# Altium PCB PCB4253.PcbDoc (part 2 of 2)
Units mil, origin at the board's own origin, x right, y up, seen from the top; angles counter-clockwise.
Board outline 1181.1 x 2007.87 mil, 6 copper layers (Top Layer, Signal Layer 2, GND Layer 3, PWR Layer 4, Signal Layer 5, Bottom Layer), stack 65.197 mil thick; 84 components, 108 nets, 396 pads, 435 vias.
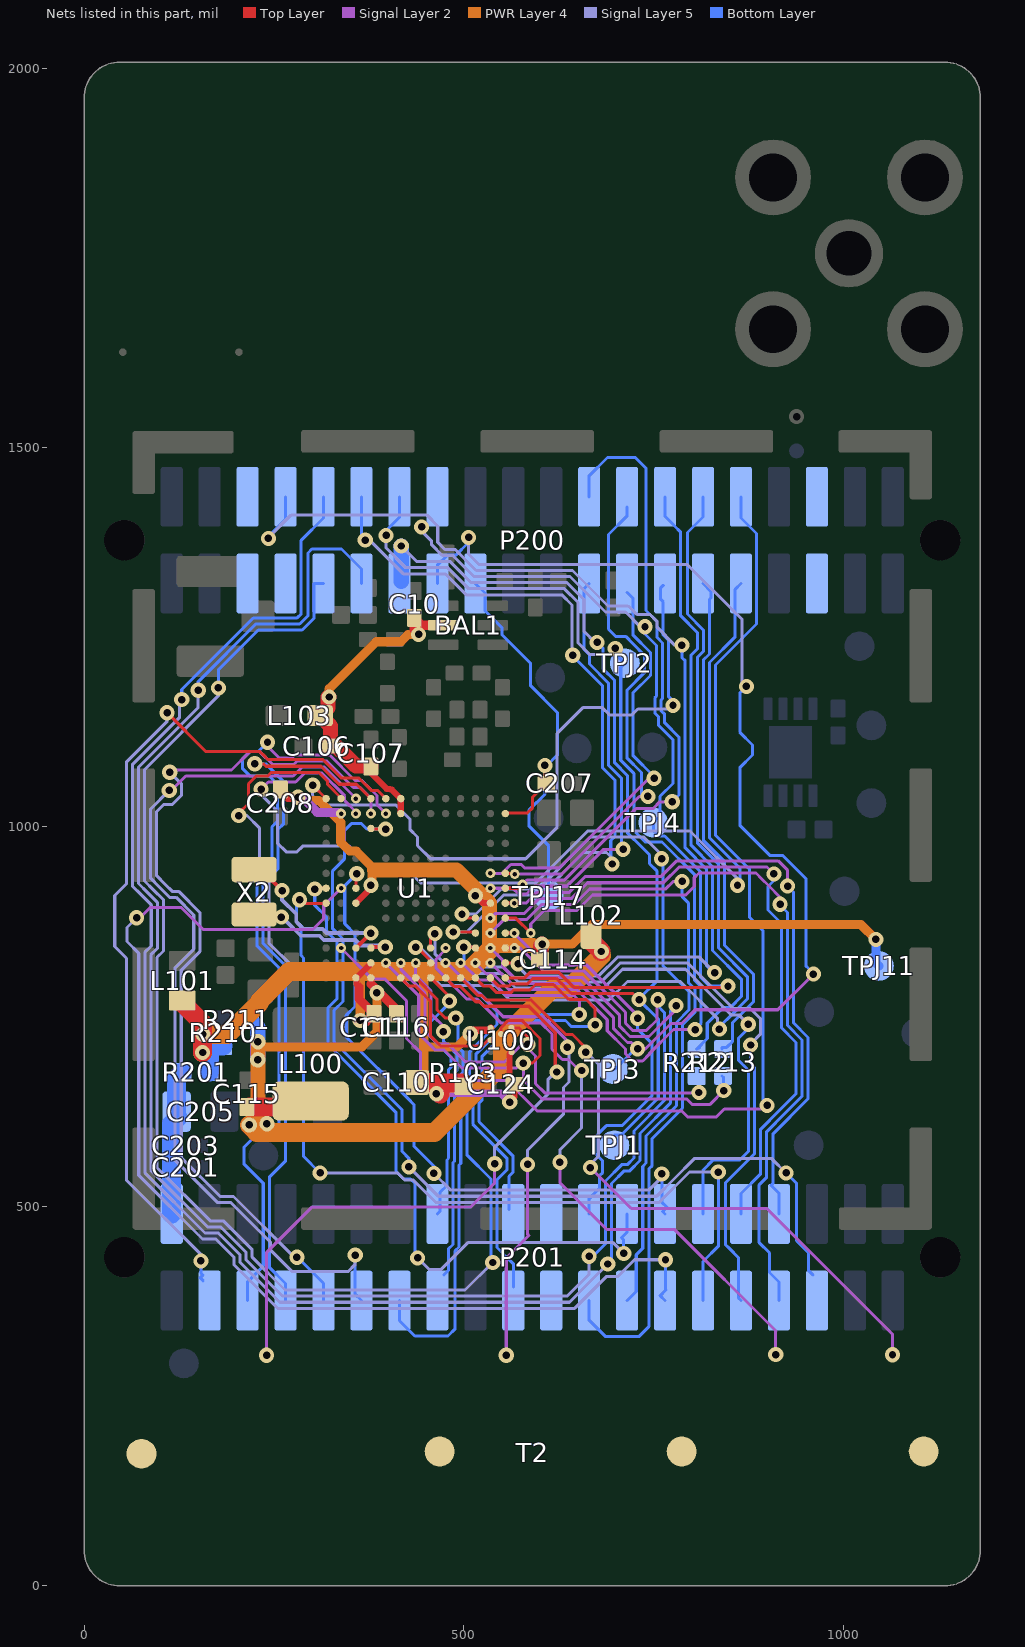
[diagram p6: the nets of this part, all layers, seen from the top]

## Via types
v1: diameter 20, hole 9.84, Top Layer to Bottom Layer, tented both sides, 403 vias
v2: diameter 13/13 (per signal layer), hole 5.91, Top Layer to Signal Layer 2, tented both sides, 31 vias
v3: diameter 13/13 (per signal layer), hole 5.91, Top Layer to Signal Layer 2, tented top, 1 vias

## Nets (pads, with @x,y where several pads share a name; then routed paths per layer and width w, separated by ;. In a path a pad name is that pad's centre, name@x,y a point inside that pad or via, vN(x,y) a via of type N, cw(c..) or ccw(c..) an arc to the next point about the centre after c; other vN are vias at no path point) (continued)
RADIO_PB13: P200.32 U1.C12 | length 1562
  Signal Layer 2 w4: v2(338.58,840.55) 379.2,799.94 395.94,799.94 425,770.88 425,721.22 443.54,702.68 443.54,678.58 456.13,665.99 556.68,665.99 596.95,625.72 787.54,625.72 795.09,618.17 833.42,618.17 843.56,628.31 895.09,628.31 v1(900,633.22)
  Bottom Layer w4: P200.32@865.55,1435.04 865.55,1407.13 886.12,1386.56 886.12,1267.47 832,1213.35 832,989.04 877,944.04 877,880.69 894.82,862.87 894.82,640.26 v1@900,635.08
RADIO_PB14: U1.C11 X2.2 | length 233.7
  Top Layer w5: X2.2@224.08,942.91 X2.2@228.35,942.91 ; X2.2@224.08,943.85 233.37,943.85 v1(261,916.22) ; U1.C11@358.27,840.55 v1(377.95,860.24)
  Signal Layer 5 w5: v1(261,916.22) 261,903.89 279.5,885.39 279.5,875.39 281.3,873.59 289.17,865.72 314.04,865.72 319.53,860.24 v1(377.95,860.24)
RADIO_PB15: U1.C10 X2.1 | length 227.4
  Top Layer w5: X2.1@202.38,884.07 202.54,884.22 205.54,881.22 X2.1@224.08,881.22 ; X2.1@224.08,884.79 256.43,884.79 v1(260,881.22) ; U1.C10@377.95,840.55 379.92,842.52 380.65,841.79 v1(396.91,841.79)
  Signal Layer 5 w5: v1@267.5,874.66 285.44,856.72 310.31,856.72 315.8,851.24 357.49,851.24 364.99,843.74 398.85,843.74 v1(396.91,841.79)
RADIO_PC0: T2.1 U1.A5 | length 891.2
  Top Layer w4: U1.A5@476.38,801.18 487.91,789.65 496.28,789.65 516.2,769.73 521.12,769.73 527.03,763.83 585.95,763.83 620.84,728.94 620.84,681.38 622.37,682.91 623.06,682.22 622.08,681.23 v1@626.58,676.73 ; v1(623.06,677.2) v1@626.11,677.2
  Signal Layer 2 w4: v1(240.57,303.95) 240.57,439.64 300.1,499.17 509.19,499.17 541.05,531.03 v1(541.05,556.34)
  Signal Layer 5 w4: v1(541.05,556.34) 541.05,578.1 611.54,648.59 611.54,667.65 621.09,677.2 v1(623.06,677.2)
RADIO_PC1: T2.2 U1.B5 | length 654
  Signal Layer 2 w4: v2(476.38,820.87) 478.51,820.87 483.56,815.81 483.56,815.69 518.18,781.07 521.25,781.07 552.34,749.97 605.22,749.97 636.84,718.35 v1(636.84,709.68) ; v1(556.31,303.99) 556.31,432.04 586,461.74 584.45,463.29 v1(584.45,555.48)
  Signal Layer 5 w4: v1(584.45,555.48) 584.45,574.39 631.55,621.49 631.79,621.49 631.79,656.73 639.06,664 639.06,683.83 639.11,683.87 639.11,707.42 v1(636.84,709.68)
RADIO_PC2: T2.3 U1.C5 | length 847.8
  Signal Layer 2 w4: v3(476.38,840.55) 476.38,838.54 463.88,826.04 463.88,813.64 504.44,773.07 517.93,773.07 549.04,741.97 601.23,741.97 601.91,741.97 616.68,727.2 616.68,707.21 630.21,693.68 638.29,693.68 652.8,679.17 v1(655.54,679.17) ; v1(627,558.39) 627,531.26 639.32,518.94 688.35,469.91 777.7,469.91 911.76,335.85 911.33,335.41 v1(911.33,304.83)
  Signal Layer 5 w4: v1(627,558.39) 627,574.91 655.54,603.46 v1(655.54,679.17)
RADIO_PC3: T2.4 U1.A4 | length 891.8
  Top Layer w4: U1.A4@496.06,801.18 519.51,777.73 524.43,777.73 530.34,771.83 589.27,771.83 634.58,726.51 643.47,726.51 661.45,708.53 660.87,707.95 v1(660.87,703.2) ; v1@1067.92,306.03 v1@1069.53,304.42
  Signal Layer 2 w4: v1(667.27,551.21) 721.09,497.38 899.65,497.38 1065.21,331.83 v1(1065.21,304.56)
  Signal Layer 5 w4: v1(660.87,703.2) 662.03,703.2 677.86,687.37 677.86,566.1 667.27,555.52 v1(667.27,551.21)
RADIO_PC4: P201.19 U1.B4 | length 694.3
  Signal Layer 2 w4: v2(496.06,820.87) 498.07,820.87 520.67,798.27 535.98,798.27 556.29,777.95 645.44,777.95 652.59,770.8 v1(652.59,752.99)
  Bottom Layer w4: P201.19@565.55,393.86 565.55,424.6 544.12,446.03 544.12,535.08 557.05,548.02 557.05,563.65 512.34,608.37 512.34,615 512.39,615.05 512.39,639.17 516.15,642.93 516.15,700.64 568.49,752.99 v1(652.59,752.99)
RADIO_PC5: P201.20 U1.A3 | length 601.3
  Top Layer w4: U1.A3@515.75,801.18 526.67,790.26 535.04,790.26 543.08,782.22 562.91,782.22 565.88,785.18 587.31,785.18 594.72,792.59 618.79,792.59 638.71,772.68 661.28,772.68 673.26,760.7 v1(673.26,739.21)
  Bottom Layer w4: P201.20@560,495.71 560,539.65 565.05,544.7 565.05,566.97 520.34,611.68 520.39,611.73 520.39,635.86 524.15,639.62 524.15,697.33 571.81,744.99 634.31,744.99 642.31,736.99 671.04,736.99 v1(673.26,739.21)
RADIO_PC6: R213.1 U1.B9 U100.D2 | length 719.8
  Top Layer w4: U100.D2@549.51,727.19 549.51,735.61 559.1,745.2 576.71,745.2 600.67,721.23 600.67,698.79 590.89,689.01 v1(578.77,689.01)
  Signal Layer 2 w4: v2(397.64,820.87) 441,777.5 441,727.85 462.76,706.08 474.39,706.08 498,682.48 569.54,682.48 v1@578.05,690.99 ; v1(578.77,689.01) 578.77,666.54 603.58,641.72 794.16,641.72 801.71,634.17 824.25,634.17 v1(842.77,652.69)
  Bottom Layer w4: R213.1@840.6,671.86 842.77,669.69 v1(842.77,652.69)
RADIO_PC7: U1.A8 U100.C3 | length 185.5
  Top Layer w4: U1.A8@417.32,801.18 428.24,790.26 436.62,790.26 456.79,770.09 456.79,724.38 469.56,711.61 512.7,711.61 512.74,711.57 524.75,711.57 532.5,719.31 U100.C3@535.74,719.31
RADIO_PC8: R212.1 U1.B8 U100.E1 | length 577.4
  Top Layer w4: U100.E1@563.29,735.06 572.78,735.06 584.67,723.17 584.6,723.1 584.67,723.02 v1(584.67,713.62)
  Signal Layer 2 w4: v2(417.32,820.87) 417.32,812.49 449,780.82 449,731.16 466.08,714.08 479.33,714.08 502.94,690.48 553.92,690.48 578.05,714.6 583.69,714.6 v1(584.67,713.62) ; v1@581.53,711.46 594.77,698.22 594.77,661.85 606.9,649.72 809.7,649.72 v1(810.15,650.17)
RADIO_PC9: P201.13 U1.A7 | length 612.8
  Top Layer w4: U1.A7@437.01,801.18 464.79,773.4 464.79,759.57 476.21,748.15 v1(489.69,748.15)
  Bottom Layer w4: P201.13@415.55,375.98 415.55,349.56 435.86,329.25 479.53,329.25 489,338.72 489,441.58 494.12,446.69 494.12,554.72 496.34,556.94 496.34,673.53 499.54,676.74 499.54,703.25 492.88,709.91 492.88,744.95 v1(489.69,748.15)
RADIO_PC10: P201.15 U1.B7 | length 438.7
  Signal Layer 2 w4: v2(437.01,820.87) 437.01,804.12 457,784.13 457,753.9 v1@476.81,734.09
  Bottom Layer w4: v1(473.45,730.35) 473.45,718.03 491.54,699.94 491.54,680.05 488.34,676.85 488.34,560.26 486.12,558.04 486.12,450.01 480,443.89 480,415.62 P201.15@474,409.62
RADIO_PC11: P201.16 U1.A6 | length 365.7
  Top Layer w4: U1.A6@456.69,801.18 487.06,770.82 488.98,772.74 486.5,775.22 481.99,770.71 v1(481.32,770.71)
  Bottom Layer w4: P201.16@465.55,490.16 469.01,493.61 469.01,518.56 478.12,527.67 478.12,561.35 480.34,563.57 480.34,680.16 483.54,683.37 483.54,696.62 456.46,723.7 456.46,743.06 481.32,767.92 v1(481.32,770.71)
RADIO_PD8: P201.3 U1.N9 | length 1167.9
  Top Layer w4: v1(109.51,1150.53) 160.81,1099.22 231.63,1099.22 235.09,1095.76 235.36,1095.76 242.46,1088.65 314.9,1088.65 339.23,1064.32 362.35,1064.32 378.35,1048.32 386.72,1048.32 U1.N9@397.64,1037.4
  Signal Layer 5 w4: v1(109.51,1150.53) 109.51,1139.21 55.7,1085.41 55.7,924.94 40.47,909.7 40.47,842.58 56.07,826.98 56.07,534.53 157,433.6 154.86,431.46 156.57,429.75 155.03,428.22 v1(154,428.22)
  Bottom Layer w4: v1(154,428.22) 154,412.14 156.57,409.57 152.99,406 P201.3@157,401.99
RADIO_PD9: P201.5 U1.M9 | length 1070.9
  Signal Layer 2 w4: v1(241.72,1111.76) 241.72,1106.5 257.65,1090.57 273.27,1090.57 277.72,1095.02 323.28,1095.02 357.02,1061.27 366.08,1061.27 385.95,1041.4 385.95,1029.4 v2(397.64,1017.72)
  Bottom Layer w4: P201.5@215.55,375.98 215.55,400.85 236.12,421.42 236.12,530.71 210.54,556.29 210.54,577.57 224.41,591.44 ; 225.91,592.94 247.59,592.94 257.17,602.52 257.17,814.17 227.89,843.45 227.89,928.36 247.6,948.08 247.6,1000.2 255,1007.59 255,1056.34 244.12,1067.22 218.21,1067.22 218.21,1067.38 209,1076.59 209,1089.85 218.37,1099.22 229.19,1099.22 v1(241.72,1111.76)
RADIO_PD10: P201.7 U1.N10 | length 944.3
  Top Layer w4: v1(225,1083.22) 236.58,1083.22 239.79,1080.01 312.23,1080.01 335.92,1056.32 359.03,1056.32 U1.N10@377.95,1037.4
  Bottom Layer w4: v1(225,1083.22) 239.43,1083.22 263,1059.65 263,1004.28 255.6,996.88 255.6,944.76 235.89,925.05 235.89,846.76 265.17,817.48 265.17,559.56 244.12,538.5 244.12,419.84 265.55,398.41 P201.7@265.55,375.98
RADIO_PD11: P201.9 U1.M10 | length 1196.3
  Signal Layer 2 w4: v1(113,1072.22) 115.95,1075.17 194.32,1075.17 218.37,1099.22 231.63,1099.22 248.27,1082.57 276.59,1082.57 281.03,1087.02 319.97,1087.02 354.87,1052.11 363.93,1052.11 377.95,1038.09 v2(377.95,1017.72)
  Signal Layer 5 w4: v1(113,1072.22) 128.23,1056.99 128.23,1041.59 116.27,1029.64 104.96,1029.64 95.7,1020.38 95.7,935.6 107.19,924.11 116.03,915.27 124.72,915.27 152.56,887.42 152.56,835.78 128.07,811.28 128.07,564.35 179.38,513.04 196.85,513.04 276.8,433.09 v1(280.53,433.09)
  Bottom Layer w4: v1(280.53,433.09) 274.84,433.09 273.14,434.79 276.35,437.99 292.99,421.35 307.93,406.41 315.55,398.79 P201.9@315.55,375.98
RADIO_PD12: P201.11 U1.N11 | length 1195.9
  Signal Layer 2 w4: v1(112.23,1048.22) 115.16,1048.22 134.11,1067.17 237.44,1067.17 ; 237.45,1067.16 275.52,1067.16 287.38,1079.02 316.65,1079.02 v2(358.27,1037.4)
  Signal Layer 5 w4: v1(112.23,1048.22) 87.7,1023.7 87.7,932.28 99.19,920.8 112.72,907.27 121.4,907.27 144.56,884.11 144.56,839.09 120.07,814.59 120.07,561.04 176.06,505.04 193.53,505.04 245.49,453.08 245.49,443.08 274.42,414.15 347.72,414.15 357.3,423.74 v1(357.3,436.04)
  Bottom Layer w4: v1(357.3,436.04) 357.3,384.23 P201.11@365.55,375.98
RADIO_PD13: P200.31 U1.M11 | length 1377.5
  Signal Layer 2 w4: v1(233.3,1049.68) 242.77,1059.16 278.83,1059.16 290.7,1071.02 313.34,1071.02 343.35,1041 343.35,1034.64 358.27,1019.72 v2(358.27,1017.72)
  Signal Layer 5 w4: v1(233.3,1049.68) 233.3,1042.55 255,1020.85 255,978.59 266.37,967.22 280.63,967.22 288.07,974.66 349.66,974.66 374.9,949.43 420.23,949.43 443.51,926.15 595.07,926.15 663.69,994.77 798.31,994.77 866,927.09 862.13,923.22 v1(861,923.22)
  Bottom Layer w4: v1(861,923.22) 864.2,923.22 864.2,945.53 824,985.73 824,1216.66 857.87,1250.53 857.87,1313.18 P200.31@865.55,1320.87
RADIO_PD14: P200.30 U1.N12 | length 1821.8
  Top Layer w4: v1(203.9,1015.06) 203.9,1018.12 216.62,1030.84 216.62,1056.91 226.93,1067.22 242.08,1067.22 246.64,1071.78 309.15,1071.78 321,1059.93 321,1055.85 338.58,1038.27 U1.N12@338.58,1037.4
  Signal Layer 5 w4: v1(203.9,1015.06) 214.79,1015.06 231,998.85 231,959.76 244,946.76 244,846.55 274.22,816.33 444.81,816.33 469.92,791.22 541.74,791.22 561.02,771.94 691.51,771.94 716.1,796.54 785.75,796.54 834.88,747.41 834.88,741 840.25,735.63 v1@838.84,734.22 ; v1(837.12,733.63) 838.25,733.63 v1@838.84,734.22 ; v1@838.98,734.08 v1@838.84,734.22
  Bottom Layer w4: P200.30@815.55,1435.04 815.55,1408.51 794.98,1387.95 794.98,1280.72 816.03,1259.67 816.03,1231.32 808,1223.29 808,979.1 836.13,950.97 836.13,840.56 874,802.69 874,773.28 854.65,753.93 854.57,753.93 838,737.36 840.15,735.21 838.98,734.04 838.8,734.22 838.2,733.63 v1(837.12,733.63)
RADIO_PD15: P200.27 U1.N13 | length 889.6
  Top Layer w4: v1(301.28,1055.02) U1.N13@318.9,1037.4
  Signal Layer 5 w4: v1(301.28,1055.02) 301.28,1040.87 312.93,1029.22 410.59,1029.22 429.33,1010.47 429.33,996.83 439.48,986.68 439.48,975.43 456.76,958.15 581.81,958.15 623.37,999.71 623.37,1123.44 657.19,1157.26 682.86,1157.26 692.7,1147.42 721.65,1147.42 729.65,1155.42 771.2,1155.42 v1(776,1160.22)
  Bottom Layer w4: P200.27@763.15,1318.46 759.76,1315.07 759.76,1300.06 763.09,1296.73 763.09,1252.98 770.28,1245.79 770.28,1171.45 v1@777.25,1164.48
RADIO_PF0: P200.14 TPJ2.1 U1.B3 | length 1426
  Signal Layer 2 w4: v2(515.75,820.87) 530.35,806.27 539.29,806.27 559.61,785.95 649.27,785.95 689.37,745.86 689.37,731.5 713.37,707.5 713.37,701.08 722.74,691.71 735.99,691.71 745.37,701.08 745.37,701.96 776.57,733.16 776.61,733.12 v1(805.12,733.12)
  Signal Layer 5 w4: v1(398,1384.22) 398,1367.59 424,1341.59 479.32,1341.59 506.96,1313.95 632.9,1313.95 651,1295.86 651,1242.45 666.23,1227.22 692,1227.22 v1(700,1235.22)
  Bottom Layer w4: v1(398,1384.22) 404.43,1384.22 405.25,1385.03 404.28,1385.03 398.39,1390.92 415.55,1408.07 P200.14@415.55,1435.04 ; v1(700,1235.22) 698.87,1235.22 696,1232.35 TPJ2.1@712.6,1215.75 707.13,1210.28 707.13,1155.62 707.13,1122.38 707.13,1087.85 724.31,1070.67 724.31,995.27 739.36,980.22 761.63,980.22 804.13,937.71 804.13,798.48 813.12,789.5 813.12,741.53 805.12,733.53 v1(805.12,733.12)
RADIO_PF1: P200.13 TPJ1.1 U1.A2 | length 1340.5
  Top Layer w4: U1.A2@535.43,801.18 546.4,790.22 559.6,790.22 562.56,793.18 584,793.18 591.41,800.59 622.11,800.59 642.02,780.68 723.33,780.68 v1(731.33,772.68)
  Signal Layer 5 w4: v1(418,1370.22) 438.63,1349.59 482.64,1349.59 510.27,1321.95 636.22,1321.95 659,1299.17 659,1257.48 v1@672.95,1243.52
  Bottom Layer w4: v1(676,1243.22) 684,1235.22 684,1208.02 699.13,1192.89 699.13,1152.3 699.13,1125.7 699.13,1084.54 715.88,1067.79 715.88,992.38 736.05,972.22 745,963.27 745,951.59 755.08,941.51 755.08,797.3 731.33,773.56 v1(731.33,772.68) ; TPJ1.1@698.82,580.71 698.82,594.2 707.94,594.2 756.56,642.82 756.56,746.89 730.96,772.49 v1@730.34,772.49
  Bottom Layer w20: P200.13@418,1323.31 v1(418,1370.22)
RADIO_PF2: P200.15 TPJ3.1 U1.B2 | length 1600
  Signal Layer 2 w4: v2(535.43,820.89) 535.98,820.89 562.92,793.95 652.58,793.95 697.37,749.17 697.37,734.81 716.11,716.07 721.01,716.07 v1(729.37,707.71) 739.8,707.71 773.3,741.21 787.14,741.21 805.15,759.22 914.13,759.22 v1(961.06,806.14)
  Signal Layer 5 w4: v1(506.58,1381.61) 506.58,1359.59 520.21,1345.95 794.6,1345.95 866.83,1273.72 866.83,1191.04 v1(872.73,1185.14)
  Bottom Layer w4: P200.15@465.55,1320.87 465.55,1344.88 478.83,1358.16 489.93,1358.16 506.58,1374.81 v1(506.58,1381.61) ; TPJ3.1@696.85,681.1 699.88,681.1 727,708.22 728,707.22 728.49,707.71 v1(729.37,707.71) 730.49,707.71 v1@732,709.22 ; v1(872.73,1185.14) 864,1176.41 864,1124.95 880.81,1108.14 880.81,1094.97 864,1078.16 864,1002.3 904.05,962.25 920.91,962.25 951,932.16 951,817.08 v1@955.28,812.8
RADIO_PF3: P200.16 TPJ4.1 U1.A1 | length 1223.6
  Top Layer w4: U1.A1@555.12,801.18 580.69,801.18 588.1,808.59 625.42,808.59 645.34,788.68 846.75,788.68 v1(848.47,790.39)
  Signal Layer 5 w4: v1(444.74,1395.32) 448.19,1395.32 448.19,1386.51 458.04,1376.66 458.04,1371.68 472.13,1357.59 485.95,1357.59 513.59,1329.95 640.26,1329.95 687,1283.22 713.63,1283.22 732.95,1263.9 v1(739.09,1263.9)
  Bottom Layer w4: v1(739.09,1263.9) 739.09,1254.36 754.28,1239.16 754.28,1172.44 752,1170.16 752,1150.28 757,1145.28 757,1134.01 776,1115.01 776,1057.32 759,1040.32 759,1026.59 759.04,1026.56 759.04,1014.94 TPJ4.1@750,1005.91 750,995.48 757.26,988.22 764.94,988.22 812.13,941.03 812.13,801.79 823.53,790.39 v1(848.47,790.39)
RADIO_PF4: P200.23 U1.G2 | length 577
  Signal Layer 2 w4: v2(535.43,919.29) 565,919.29 572.58,911.71 582.99,911.71 593.22,921.94 636.03,921.94 684.7,970.61 v1(710.3,970.61)
  Bottom Layer w4: P200.23@665.55,1320.87 659,1314.31 659,1233.85 665.99,1226.86 665.99,1214.72 691.13,1189.57 691.13,1148.99 691.13,1129.01 691.13,1081.22 707.88,1064.48 707.88,972.33 709.61,970.61 v1(710.3,970.61)
RADIO_PF5: P200.24 U1.G1 | length 852.8
  Top Layer w4: U1.G1@555.12,919.29 572.83,919.29 v2(577.76,924.21) ; v2@577.42,925.2 v2@577.76,924.86 ; v2(577.76,924.21) 578.08,924.54 v2@577.76,924.86 ; v2(577.76,924.21) v2@577.76,924.86
  Signal Layer 2 w4: v2@579.12,922.85 v2(577.76,924.21) 583.49,929.94 632.72,929.94 727,1024.22 749.63,1024.22 758.63,1033.22 v1(775,1033.22)
  Bottom Layer w4: P200.24@665.55,1435.04 665.55,1462.8 689.71,1486.95 726.32,1486.95 740.47,1472.81 740.47,1285.24 755.09,1270.61 755.09,1249.67 762.28,1242.48 762.28,1169.13 760,1166.85 760,1153.59 765,1148.59 765,1137.32 784,1118.32 784,1042.22 v1(775,1033.22)
RADIO_PF6: P200.25 U1.H2 | length 549.9
  Signal Layer 2 w4: v2(535.43,938.98) 550.8,938.98 562.27,950.44 576.17,950.44 580.67,945.94 626.09,945.94 744.37,1064.22 v1(751,1064.22)
  Bottom Layer w4: P200.25@715.55,1309.06 723,1301.61 723,1253.16 746.28,1229.88 746.28,1199.72 723.13,1176.57 723.13,1115.76 723.13,1094.48 751,1066.61 v1(751,1064.22)
RADIO_PF7: P200.26 U1.H1 | length 672.6
  Top Layer w4: U1.H1@555.12,938.98 566.41,938.98 v2(567.44,937.94)
  Signal Layer 2 w4: v2(567.44,937.94) 629.41,937.94 731.69,1040.22 v1(743,1040.22)
  Bottom Layer w4: P200.26@715.55,1421.81 715.55,1409.92 691,1385.37 691,1260.59 700.37,1251.22 713.63,1251.22 723,1241.85 723,1241.67 738.28,1226.39 738.28,1203.03 715.13,1179.88 715.13,1158.93 715.13,1119.07 715.13,1091.17 734.6,1071.7 734.6,1040.22 v1@739.8,1040.22
RADIO_PF8: P200.8 U1.B1 | length 1494.4
  Top Layer w4: U1.B1@555.12,820.87 573.35,820.87 574.83,819.39 577.19,821.75 575.36,819.92 v1(571.88,819.92)
  Signal Layer 5 w4: v1(243,1380.22) 243,1381.19 273.13,1411.32 451.37,1411.32 466.04,1396.65 466.04,1375 475.45,1365.59 489.26,1365.59 516.9,1337.95 643.58,1337.95 690.31,1291.22 716.94,1291.22 728.26,1279.9 745.72,1279.9 755.09,1270.53 755.09,1263 778.48,1239.61 v1(787.69,1239.61) ; v1(571.88,819.92) 576.8,819.92 577.19,820.31 574.89,818.02 575,818.02 572.42,815.43 570.07,817.79 570,817.72 583.78,803.94 678.25,803.94 702.85,828.54 810.45,828.54 v1(830.88,808.11)
  Bottom Layer w4: v1@241.14,1380.91 265.55,1405.31 P200.8@265.55,1435.04 ; v1(787.69,1239.61) 787.69,1223.4 792,1219.08 792,972.48 820.13,944.34 820.13,817.09 830.88,806.34 v1(830.88,808.11)
RADIO_PF9: P200.9 U1.C3 | length 1932.7
  Top Layer w4: v1(500.33,841.76) 514.54,841.76 U1.C3@515.75,840.55
  Signal Layer 5 w4: v1(177,1183.22) 177,1172.77 79.7,1075.47 79.7,928.97 91.19,917.49 104.56,904.11 104.56,836.7 96.07,828.2 96.07,551.1 166.12,481.04 183.59,481.04 221.49,443.14 221.49,433.14 264.8,389.83 502.04,389.83 v1(538.41,426.2)
  Bottom Layer w4: v1(177,1183.22) 177,1206.71 229.73,1259.44 287.46,1259.44 302.98,1274.96 302.98,1320.87 P200.9@315.55,1320.87 ; v1(500.33,841.76) 500.33,800.17 544.02,756.48 544.02,739.82 508.15,703.96 508.15,646.25 504.39,642.49 504.39,618.36 504.34,618.31 504.34,605.06 504.34,567.99 536.12,536.21 536.12,428.5 v1(538.41,426.2)
RADIO_PF10: P200.10 U1.C2 | length 2457.6
  Signal Layer 2 w4: v2(535.43,840.55) 551.1,824.89 551.1,817.09 566.24,801.95 655.9,801.95 705.37,752.49 705.37,738.13 719.43,724.07 744.43,724.07 780.12,759.76 v1(780.12,764.69)
  Signal Layer 5 w4: v1(128.73,1167.88) 125.51,1164.65 125.51,1143.9 63.7,1082.1 63.7,922.34 75.19,910.86 88.56,897.49 88.56,843.32 80.07,834.83 80.07,544.47 159.5,465.04 176.96,465.04 205.49,436.51 205.49,426.52 258.18,373.83 639.61,373.83 v1(690,424.22)
  Bottom Layer w4: v1(128.73,1167.88) 128.73,1181.07 223.1,1275.44 256.75,1275.44 256.81,1275.5 280.9,1275.5 286.12,1280.72 286.12,1377.65 315.55,1407.09 P200.10@315.55,1435.04 ; v1(690,424.22) 694.98,429.2 694.98,530.31 711.7,547.02 719.06,547.02 732.5,560.47 732.5,596.14 772.56,636.2 772.56,757.13 v1(780.12,764.69)
RADIO_PF11: P200.11 U1.C1 | length 2419.1
  Top Layer w4: U1.C1@555.12,840.55 v2(566.93,840.55)
  Signal Layer 2 w4: v2(566.93,840.55) 574.77,840.55 605.37,809.95 659.21,809.95 713.37,755.8 713.37,741.44 722.74,732.07 741.12,732.07 754.87,745.82 754.87,771.07 v1(756.12,772.33)
  Signal Layer 5 w4: v1(150.42,1180.13) 150.42,1157.5 71.7,1078.78 71.7,925.66 83.19,914.17 96.56,900.8 96.56,840.01 88.07,831.52 88.07,547.79 162.81,473.04 180.28,473.04 213.49,439.83 213.49,429.83 261.49,381.83 636.3,381.83 665.48,411.02 v1(665.48,434.35)
  Bottom Layer w4: v1(150.42,1180.13) 150.42,1191.44 226.42,1267.44 284.15,1267.44 294.98,1278.27 294.98,1361.01 300.21,1366.24 339.3,1366.24 365.55,1339.98 P200.11@365.55,1320.87 ; v1(665.48,434.35) 670.46,434.35 686.98,450.87 686.98,533.62 708.39,555.02 715.74,555.02 724.5,563.78 724.5,599.45 764.56,639.51 764.56,755.57 756.12,764.01 v1(756.12,772.33)
RADIO_PF12: P200.12 U1.D3 | length 1028.9
  Top Layer w4: v1(486.25,861.63) 514.35,861.63 U1.D3@515.75,860.24
  Signal Layer 5 w4: v1(370.62,1377.95) 376.33,1377.95 420.69,1333.59 476.01,1333.59 503.64,1305.95 629.59,1305.95 643,1292.54 643,1227.22 v1(644,1226.22) ; v1(486.25,861.63) 504.2,861.63 552.71,910.15 601.7,910.15 658.02,966.47 688.33,966.47 695.72,959.08 v1(695.72,951.25)
  Bottom Layer w4: P200.12@365.55,1435.04 365.55,1383.02 v1(370.62,1377.95) ; v1(644,1226.22) 644,1225.39 683.13,1186.26 683.13,1145.67 683.13,1132.33 683.13,1077.91 699.88,1061.16 699.88,988.06 693.96,982.14 693.96,953.01 v1(695.72,951.25)
RADIO_PF13: P201.23 U1.D2 | length 1018.6
  Signal Layer 2 w4: v2(535.43,860.24) 553.02,877.83 583.05,877.83 603.16,897.94 645.98,897.94 666.55,918.52 766.55,918.52 776.25,928.22 v1(788,928.22)
  Bottom Layer w4: P201.23@665.55,375.98 665.55,350.09 687.22,328.42 730.87,328.42 744.12,341.67 744.12,549.46 748.5,553.84 748.5,589.51 788.56,629.57 788.56,739.19 805.12,755.74 805.12,786.18 796.13,795.17 796.13,900.02 788,908.16 v1(788,928.22)
RADIO_PF14: P201.24 U1.D1 | length 544
  Top Layer w4: U1.D1@555.12,860.24 v2(566.93,860.24)
  Signal Layer 2 w4: v2(566.93,860.24) 566.93,859.71 608.68,817.95 662.53,817.95 729.37,751.11 v1(729.37,748.07) v1@729.85,748.07
  Bottom Layer w4: P201.24@665.55,490.16 665.55,510.28 678.98,523.72 678.98,540.3 683.27,544.58 683.27,559.94 673.13,570.07 673.13,591.35 688.18,606.39 708.82,606.39 748.56,646.14 748.56,714.41 729.37,733.6 v1(729.37,748.07)
RADIO_PF15: P201.25 U1.E3 | length 970.7
  Top Layer w4: v1(498,885.22) 500.61,885.22 505.91,879.92 U1.E3@515.75,879.92
  Signal Layer 5 w4: v1(498,885.22) 516.47,885.22 549.4,918.15 598.38,918.15 667.01,986.77 737.45,986.77 761,963.22 v1(761,958.22)
  Bottom Layer w4: P201.25@715.55,375.98 727.6,388.03 727.6,436.27 736.12,444.79 736.12,552.77 740.5,557.16 740.5,592.82 780.56,632.88 780.56,742.5 797.12,759.06 797.12,782.87 763.08,816.9 763.08,956.14 v1(761,958.22)
RADIO_PI0: P201.26 U1.G13 | length 928
  Top Layer w4: v1(304,918.22) 305.07,919.29 U1.G13@318.9,919.29
  Signal Layer 5 w4: v1@440.42,432.27 v1(439.43,432.27) 454.47,417.22 470.82,417.22 506.38,452.79 696.43,452.79 v1(711,438.22)
  Bottom Layer w4: v1(304,918.22) 304,896.85 319.51,881.34 319.51,862.62 333.07,849.05 333.07,773.35 321.46,761.74 321.46,713.59 322.29,712.76 410.81,624.24 410.81,546.78 421.37,536.22 430.2,536.22 436.12,530.31 436.12,435.57 v1(439.43,432.27) ; v1(711,438.22) 711,455.93 708.08,458.85 715.55,466.33 P201.26@715.55,490.16
RADIO_PI1: P201.27 U1.G12 | length 1529.3
  Signal Layer 2 w4: v1(69.2,880.3) 73.87,880.3 87.63,894.06 127.78,894.06 156.69,865.14 301.55,865.14 315.82,879.42 315.82,896.53 v2(338.58,919.29)
  Signal Layer 5 w4: v1(69.2,880.3) 56.56,867.66 56.56,849.11 72.07,833.61 72.07,541.16 156.18,457.04 173.65,457.04 197.49,433.2 197.49,423.2 254.86,365.83 646.39,365.83 688.58,408.02 703.42,408.02 725.19,429.78 v1(766.1,429.78)
  Bottom Layer w4: P201.27@765.55,375.98 759.05,382.49 766.75,390.19 766.1,390.84 v1(766.1,429.78)
RADIO_PI2: P201.28 U1.G11 | length 860.8
  Top Layer w4: U1.G11@358.27,919.29 358.27,938.98 359,938.25 v1(359.27,938.48)
  Signal Layer 5 w4: v1(460.98,543.53) 483.06,521.45 744.23,521.45 761.23,538.45 v1(761.23,542.84)
  Bottom Layer w4: v1(359.27,938.48) 343.51,922.72 343.51,872.56 357.07,859 357.07,763.41 345.46,751.8 345.46,723.53 346.29,722.7 426.37,642.63 434.81,634.19 434.81,579.35 460.98,553.18 v1(460.98,543.53) ; v1(761.23,542.84) 761.23,505.73 768,498.96 762.37,493.33 P201.28@765.55,490.16
RADIO_PI3: P201.29 U1.F13 | length 1158.1
  Top Layer w4: v1(284,904.22) 284.12,904.22 284.93,903.42 280.87,899.35 282.51,899.35 286.37,903.22 290.24,899.35 318.65,899.35 U1.F13@318.9,899.61
  Signal Layer 5 w4: v1(311,544.22) 413.37,544.22 423,534.59 434.04,534.59 463.17,505.45 757.79,505.45 797.64,545.3 v1(835.67,545.3)
  Bottom Layer w4: v1(284,904.22) 280,900.22 280,875.59 286.03,869.56 286.03,843.88 ; 286,843.85 286,830.59 289.17,827.42 289.17,566.05 v1(311,544.22) ; P201.29@815.55,375.98 815.55,427.63 836.12,448.19 836.12,544.85 v1(835.67,545.3)
RADIO_PJ14: P201.30 U1.B6 | length 836.8
  Top Layer w4: v1(436.79,841.37) 438.89,841.37 456.69,823.57 U1.B6@456.69,820.87
  Signal Layer 5 w4: v1(436.79,841.37) 442.4,841.37 476.54,807.22 549.09,807.22 568.37,787.94 684.88,787.94 709.48,812.54 792.38,812.54 852.43,752.49 862.74,752.49 v1(875.04,740.19)
  Bottom Layer w4: P201.30@815.55,490.16 815.55,547.81 829.22,561.48 864.2,561.48 875.4,572.68 875.4,679.55 862,692.95 862,713.35 862.29,713.65 862.29,721.84 875.04,734.59 v1(875.04,740.19)
RADIO_PJ15: P201.31 U1.C6 | length 953.3
  Top Layer w4: U1.C6@456.09,841.16 U1.C6@456.69,840.55 456.69,853.91 v1(462.25,859.47)
  Signal Layer 5 w4: v1(462.25,859.47) 462.25,832.82 479.86,815.22 552.41,815.22 571.68,795.94 681.57,795.94 706.16,820.54 795.69,820.54 855.74,760.49 878.16,760.49 891.04,747.61 891.04,726.81 879.44,715.21 883.04,711.62 878.15,706.73 877.33,707.55 878.29,708.51 v1(878.29,712.76)
  Bottom Layer w4: P201.31@865.55,375.98 862.41,379.12 862.41,432.56 850.21,444.77 844.98,450.01 844.98,530.95 883.4,569.36 883.4,682.86 878,688.26 878,706.73 877.33,707.4 878.29,708.36 v1(878.29,712.76)
RADIO_PK0: P201.32 U1.E2 | length 902
  Signal Layer 2 w4: v2(535.43,879.92) 541.34,885.83 579.73,885.83 599.85,905.94 642.66,905.94 663.24,926.52 763.24,926.52 784.08,947.36 899.86,947.36 v1(909,938.22)
  Bottom Layer w4: P201.32@865.55,490.16 865.55,517.19 891.46,543.09 891.46,601.92 915.34,625.8 921.67,632.13 938,648.46 938,716.14 918.82,735.33 918.82,872.82 901.03,890.6 901.03,921.6 909,929.56 v1(909,938.22)
RADIO_PK1: P201.33 U1.E1 | length 1007.5
  Top Layer w4: U1.E1@555.12,879.92 568.9,879.92 v2(588.58,860.24)
  Signal Layer 2 w4: v2(588.58,860.24) 588.58,872.05 606.47,889.94 649.29,889.94 669.87,910.52 792.93,910.52 804,921.59 804,933.2 810.16,939.36 885.24,939.36 893,931.6 902.37,922.22 917.03,907.57 v1(917.03,898.22)
  Bottom Layer w4: P201.33@915.55,375.98 915.55,400.48 903.04,412.99 903.04,438.91 889.56,452.39 889.56,528.54 899.46,538.44 899.46,598.61 923.34,622.49 924.98,624.13 946,645.15 946,719.46 926.82,738.64 926.82,887.4 917.03,897.19 v1(917.03,898.22)
RADIO_PK2: P201.34 U1.F1 | length 877.6
  Top Layer w4: U1.F1@555.12,899.61 v2(566.93,899.61)
  Signal Layer 2 w4: v2(566.93,899.61) 582.2,899.61 596.53,913.94 639.35,913.94 659.93,934.52 759.93,934.52 780.77,955.36 914.49,955.36 927,942.85 v1(927,922.22)
  Bottom Layer w4: P201.34@915.55,490.16 915.55,517.52 905.24,527.83 907.46,530.05 907.46,595.29 954,641.83 954,722.77 934.82,741.95 934.82,914.6
USB_VBUS: P200.35
USB_VREG: P200.36
VBIAS: BAL1.2 C10.1 C106.1 C107.1 L103.2 U1.M8 U1.N8 | length 438.8
  Top Layer w8: C107.1@377.95,1079.72 377.95,1071.23 398.86,1050.32 402.99,1050.32 404.1,1049.21 405.51,1049.21 U1.N8@417.32,1037.4 U1.M8@417.32,1017.72 ; C10.1@435.04,1275.59 C10.1@438.01,1272.62
  Top Layer w12: v1@435.04,1260.1 C10.1@435.04,1275.59 ; C10.1@438.01,1272.62 444.88,1265.75 BAL1.2@473.41,1265.75
  Top Layer w20: v1(322.83,1171.26) 321.49,1171.26 321.49,1157.12 L103.2@311.02,1146.65 324.52,1133.15 C106.1@324.52,1106.57 332.21,1106.57 358.46,1080.32 377.95,1080.32 C107.1@377.95,1079.72
  PWR Layer 4 w12: v1(322.83,1171.26) 322.83,1182.09 384.84,1244.09 417.32,1244.09 426.97,1253.74 v1(440.76,1253.74)
VDCDC: C115.1 C116.1 L100.2 L102.1 R211.2 U1.A10 | length 1102.2
  Top Layer w8: U1.A10@377.95,801.18 377.95,793.31 378.2,793.06
  Top Layer w12: 378.2,793.31 378.2,793.06 v1@385.83,785.43 ; v1(385.83,781.5) v1@385.83,785.43 ; C116.1@411.42,753.94 411.42,759.84 v1@385.83,785.43
  Top Layer w25: C115.1@217.78,630.91 L100.2@273.6,630.91 ; L102.1@668.2,856.13 668.2,849.34 681.27,836.27 v1@681.27,835.94
  PWR Layer 4 w12: 239.48,710.09 366.08,710.09 385.83,729.84 v1(385.83,781.5)
  PWR Layer 4 w20: 229.1,608.94 v1(229.1,717.01)
  PWR Layer 4 w25: v1(217.78,607.44) 227.46,597.76 461.82,597.76 551.54,687.47 551.54,721.55 616.78,786.79 638.02,786.79 v1@681.6,830.36
  Bottom Layer w20: R211.2@218.83,746.28 228.84,736.26 v1(228.84,693.33)
  other v1: 240.97,608.94 681.6,835.94
VMCU: C110.1 C111.1 C114.1 C124.1 C208.1 L101.1 R103.1 R201.2 R210.2 TPJ11.1 U1.A11 U1.B10 U1.F2 U1.F11 U1.M12 U100.A1 U100.E3 | length 2426.6
  Top Layer w7.99: C124.1@562.54,656.42 C124.1@562.54,661.05 ; U100.A1@563.29,703.57 560.77,701.04 560.77,667.66 C124.1@567.38,661.05 567.38,644.05 v1@561.88,638.55 ; v1@561.88,638.55 v1(560.84,637.5) 562.92,637.5 v1@561.88,638.55
  Top Layer w8: U1.F11@358.27,899.61 377.95,919.29 v1(377.95,923.23) ; 362.2,789.37 359.08,792.49 359.08,800.37 U1.A11@358.27,801.18 359.09,801.18 377.95,820.05 U1.B10@377.95,820.87 ; v1(515.75,909.45) 525.59,899.61 U1.F2@535.43,899.61
  Top Layer w10: v1(508.88,727.61) 513.72,732.45 533.12,732.45 U100.E3@535.74,735.06
  Top Layer w12: C208.1@258.61,1049.27 268.66,1039.22 v1(282,1039.22) ; 362.2,789.37 362.2,773.62 C111.1@381.89,753.94 v1@371.22,743.27
  Top Layer w20: C114.1@601.72,825.66 601.72,843.87 v1(603.55,845.71)
  Top Layer w25: L101.1@129.33,768.14 156.29,741.18 ; v1(156.29,702.88) 156.29,740.74 ; C110.1@438.98,663.39 469.32,663.39 ; v1@469.32,648.47 469.32,663.39 ; R103.1@499.17,662.89 469.82,662.89 469.32,663.39
  Signal Layer 2 w10: v1@464.95,649.19 549.15,649.19 v1(560.84,637.5) ; v1@467.61,646.76 v1@469.09,648.23
  Signal Layer 2 w12: v1(282,1039.22) 287.28,1039.22 307.28,1019.22 337.08,1019.22 v2(338.58,1017.72)
  PWR Layer 4 w12: 291.71,1035.02 309.35,1035.02 338.27,1006.1 338.27,979.9 349.98,968.19 358.68,968.19 379.27,947.6 v1@379.27,924.54 ; v1(603.55,845.71) 643.19,845.71 665.62,868.14 665.77,868.14 669.06,871.42 1023.71,871.42 v1(1043.29,851.84)
  PWR Layer 4 w12.01: 362.57,809.57 364,808.14 v1(364,745.22) ; 447.54,809.57 447.54,666.83 v1@467.61,646.76 ; 448.4,710.35 491.62,710.35 v1(508.88,727.61)
  PWR Layer 4 w20: 382.78,943.29 490.87,943.29 534.27,899.89 534.27,841.46 536.12,839.61 ; 539.09,842.58 540.43,843.92 591.67,843.92 593,842.58 v1@603.55,842.58
  PWR Layer 4 w25: v1(156.29,702.88) v1@156.29,726.66 ; v1(156.59,726.66) 189.16,726.66 231.26,768.76 231.26,770.8 270.25,809.79 320.05,809.79 320.26,809.57 362.57,809.57 506.08,809.57 536.12,839.61 539.09,842.58
  Bottom Layer w12: v1(1043.29,851.84) 1043.29,820.89 TPJ11.1@1047.24,816.93
  Bottom Layer w25: v1(156.59,726.66) 156.59,703.18 164.65,711.24 R210.2@183.39,711.24 ; R201.2@165.35,677.17 v1@165.35,702.88
  other v1: 464.34,648.58
VMCU_IN: C201.1 C203.1 C205.1 P201.2 R201.1 | length 185.8
  Bottom Layer w25: P201.2@115.55,490.16 115.48,490.23 115.48,609 C205.1@123.58,617.1 ; C205.1@122.05,625 122.05,669.29 R201.1@129.92,677.17
WSTK_F4: C207.1 P200.17 TPJ17.1 U1.M1 | length 599.7
  Top Layer w4: U1.M1@555.12,1017.72 555.86,1018.46 584.12,1018.46 591.13,1025.47 591.13,1039.52 C207.1@602.71,1051.1 ; v1(607.22,1081.14) 607.22,1066.02 C207.1@612.42,1060.81 ; C207.1@608.96,1057.35 C207.1@602.71,1051.1 ; C207.1@610.24,1062.99 602.71,1055.47 C207.1@602.71,1051.1
  Bottom Layer w4: P200.17@515.55,1320.87 528.26,1308.16 528.26,1284.9 550.85,1262.31 550.85,1252.94 588.49,1215.3 588.49,1186 623.53,1150.96 623.53,1094.75 609.92,1081.14 v1(607.22,1081.14) 607.22,1043.26 586.52,1022.56 586.52,1000.91 612.2,975.22 TPJ17.1@612.2,909.45
WSTK_F15: P200.28 R212.2 | length 812.6
  Bottom Layer w4: P200.28@765.55,1435.04 765.55,1409.23 777.3,1397.48 777.3,1397.29 786.12,1388.47 786.12,1278.27 808.03,1256.36 808.03,1234.64 800,1226.6 800,975.79 828.13,947.66 828.13,837.25 866,799.38 866,776.59 851.34,761.93 841.45,761.93 821.12,741.59 821.12,738.21 821.12,722.96 821.19,722.89 821.19,721.25 R212.2@807.24,707.3 810.62,710.68 R212.2@810.62,709.03
WSTK_F16: P200.29 R213.2 | length 670
  Bottom Layer w4: P200.29@815.55,1320.87 825.77,1310.65 825.77,1301.75 824.03,1300.01 824.03,1228.01 816,1219.98 816,982.42 844.13,954.28 844.13,843.87 882,806.01 882,769.74 868.46,756.19 ; R213.2@840.6,707.29 840.6,709.72 846.78,709.72 854.29,717.23 854.29,742.07 868.42,756.19
WSTK_P18: P201.21
WSTK_P19: P201.22
WSTK_P32: P201.35 U1.L10 | length 1272.5
  Top Layer w4: U1.L10@377.95,998.03 379.86,996.12 380.96,997.22 v1(397.33,997.22)
  Signal Layer 5 w4: v1(428,552.22) 466.77,513.45 754.47,513.45 777.23,536.21 803.99,562.97 906.25,562.97 v1(925,544.22)
  Bottom Layer w4: v1(397.33,997.22) 372.65,997.22 365.5,1004.36 352.25,1004.36 342.88,994.99 342.88,957.53 327.51,942.16 327.51,865.94 341.07,852.37 341.07,770.03 329.46,758.42 329.46,716.9 330.29,716.08 418.81,627.56 418.81,572.72 428,563.53 v1(428,552.22) ; v1(925,544.22) 938.92,530.3 938.92,454.99 954.24,439.67 954.24,415.88 P201.35@960.16,409.96
WSTK_P38: P200.5
WSTK_P39: P200.6
WSTK_P40: P200.7
pads on no net: BAL1.6 P200.M1 P200.M2 P201.40 P201.M1 P201.M2 TPJ9.1 TPJ18.1 TPJ19.1 TPJ20.1 U100.C1 U200.9

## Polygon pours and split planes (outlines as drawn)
GND on Top Layer "GND_L1" (solid, remove dead copper, pour order 29): 23.81,1599.99 826.37,1599.99 ccw(c826.37,1634.13) 860.51,1634.13 860.51,1832.27 931.37,1903.14 1084.92,1903.14 1155.78,1832.27 1155.71,354.31 cw(c1135.73,354.31) 1135.73,334.33 43.65,334.33 cw(c43.65,354.16) 23.81,354.17
GND on GND Layer 3 "GND_L3" (solid, remove dead copper, pour order 25): 23.81,1599.99 826.37,1599.99 ccw(c826.37,1634.13) 860.51,1634.13 860.51,1832.27 931.37,1903.14 1084.92,1903.14 1155.78,1832.27 1155.71,348.62 cw(c1141.73,348.62) 1141.73,334.65 39.37,334.64 cw(c39.37,350.2) 23.81,350.2
GND on Bottom Layer "Bottom Layer-GND_Mesh" (hatched 90Degree grid 39.37 track 7.87, pour order 39): 27.71,323.99 27.71,54.32 ccw(c52.72,54.32) 52.73,29.3 1126.76,29.3 ccw(c1126.76,54.32) 1151.77,54.32 1151.77,323.99
GND on Bottom Layer "GND_L6" (solid, remove dead copper, pour order 24): 23.81,1599.99 826.37,1599.99 ccw(c826.37,1634.13) 860.51,1634.13 860.51,1832.27 931.37,1903.14 1084.92,1903.14 1155.78,1832.27 1155.78,325.22 23.81,325.22
GND on PWR Layer 4 "GND_L4" (solid, remove dead copper, pour order 33): 23.81,1599.99 826.37,1599.99 ccw(c826.37,1634.13) 860.51,1634.13 860.51,1832.27 931.37,1903.14 1084.92,1903.14 1155.78,1832.27 1155.71,348.62 cw(c1141.73,348.62) 1141.73,334.65 39.37,334.65 cw(c39.37,350.2) 23.81,350.2
GND on Signal Layer 2 "GND_L2" (solid, remove dead copper, pour order 37): 23.81,1599.99 826.37,1599.99 ccw(c826.37,1634.13) 860.51,1634.13 860.51,1832.27 931.37,1903.14 1084.92,1903.14 1155.78,1832.27 1155.71,348.62 cw(c1141.74,348.62) 1141.73,334.65 39.37,334.65 cw(c39.37,350.21) 23.81,350.21
GND on Signal Layer 5 "GND_L5" (solid, remove dead copper, pour order 35): 23.81,1599.99 826.37,1599.99 ccw(c826.37,1634.13) 860.51,1634.13 860.51,1832.27 931.37,1903.14 1084.92,1903.14 1155.78,1832.27 1155.71,348.62 cw(c1141.73,348.62) 1141.73,334.65 39.37,334.65 cw(c39.37,350.2) 23.81,350.2

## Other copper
Top Layer:
  region net VDCDC: 204.77,643.28 204.77,601.34 210.35,595.76 245.68,595.76 252.24,602.31 252.24,643.37
  pour cut-out: 347.5,1297.24 395.67,1297.24 395.67,1235.24 425.94,1235.24 425.94,1312.65 441.69,1312.65 441.69,1349.42 689.72,1349.42 689.72,1301.18 584.65,1301.18 584.65,1204.72 596.46,1204.72 596.46,1025.84 555.86,1025.84 555.86,801.18 395.67,801.18 395.67,729.69 319.64,729.69 319.64,1142.97 372.05,1142.97 372.05,1209.66 347.5,1234.21
Signal Layer 2:
  pour cut-out: 0,1239.47 0,1622.12 856.3,1622.12 856.3,1909.45 1181.1,1909.45 1181.1,1277.28 596.46,1277.28 596.46,1013.78 314.96,1013.78 314.96,1142.97 372.3,1142.97 372.3,1206.56 342.61,1239.47
GND Layer 3:
  pour cut-out: 119.14,1310.99 119.14,1244.06 201.95,1244.06 201.95,1254.64 252.99,1254.67 252.99,1300.67 201.99,1300.67 201.99,1310.96
  pour cut-out: 462.6,1026.57 462.6,1114.17 ccw(c453.74,1114.17) 453.74,1123.03 cw(c453.74,1132.87) 443.9,1132.87 443.9,1194.88 cw(c453.74,1194.88) 453.74,1204.72 585.62,1204.72 cw(c585.62,1193.89) 596.45,1193.9 596.66,1042.52 cw(c571.85,1042.52) 571.85,1017.72 471.46,1017.72 cw(c471.45,1026.57)
PWR Layer 4:
  pour cut-out: 462.6,1026.57 462.6,1114.17 ccw(c453.74,1114.17) 453.74,1123.03 cw(c453.74,1132.87) 443.9,1132.87 443.9,1194.88 cw(c453.74,1194.88) 453.74,1204.72 585.62,1204.72 cw(c585.62,1193.89) 596.45,1193.9 596.66,1042.52 cw(c571.85,1042.52) 571.85,1017.72 471.46,1017.72 cw(c471.45,1026.57)
Signal Layer 5:
  pour cut-out: 462.6,1026.57 462.6,1114.17 ccw(c453.74,1114.17) 453.74,1123.03 cw(c453.74,1132.87) 443.9,1132.87 443.9,1194.88 cw(c453.74,1194.88) 453.74,1204.72 585.62,1204.72 cw(c585.62,1193.89) 596.45,1193.9 596.66,1042.52 cw(c571.85,1042.52) 571.85,1017.72 471.46,1017.72 cw(c471.45,1026.57)
Bottom Layer:
  pour cut-out: 938.78,1572.24 cw(c938.78,1540.75) 970.28,1540.75 cw(c938.78,1540.75) 938.78,1509.25 cw(c938.78,1540.75) 907.28,1540.75 cw(c938.78,1540.75)

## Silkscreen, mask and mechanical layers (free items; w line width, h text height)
Top Overlay:
  lines w3.94: 1181.1,39.37 1181.1,1960.63 ccw(c1133.86,1960.63) 1133.86,2007.87 47.24,2007.87 ccw(c47.24,1960.63) 0,1960.63 0,39.37 ccw(c39.37,39.37) 39.37,0 1133.86,0 ccw(c1133.86,47.24) 1181.1,47.24
Bottom Overlay:
  lines w3.94: 0,39.37 0,1960.63 cw(c47.24,1960.63) 47.24,2007.87 1133.86,2007.87 cw(c1133.86,1960.63) 1181.1,1960.63 1181.1,43.31 ; 0,47.24 ccw(c47.24,47.24) 47.24,0 1133.86,0 ccw(c1133.86,47.24) 1181.1,47.24
Top Solder:
  drawing of 282 lines, arcs and shapes, not listed
Bottom Solder:
  drawing of 282 lines, arcs and shapes, not listed
BOARD OUTLINE 1:
  drawing of 282 lines, arcs and shapes, not listed
Mechanical 2:
  lines w3.94: -19.68,-19.69 19.69,-19.69 ; 0,-39.37 0,0
EXT_SILKP 21:
  region: 834.04,52.08 819.49,52.08 819.49,268.71 834.04,268.71
  region: 794.65,52.08 780.12,52.08 780.12,263.78 794.65,263.78
  region: 755.29,52.08 740.76,52.08 740.76,258.86 755.29,258.86
  region: 715.92,52.08 701.39,52.08 701.39,253.95 715.92,253.95
  region: 676.55,52.08 662.03,52.08 662.03,249.03 676.55,249.03
  region: 637.19,52.08 622.64,52.08 622.64,244.1 637.19,244.1
  region: 597.82,52.08 583.27,52.08 583.27,239.17 597.82,239.17
  region: 1109.63,52.08 1095.1,52.08 1095.1,303.15 1109.63,303.15
  region: 1070.26,52.08 1055.71,52.08 1055.71,298.25 1070.26,298.25
  region: 1030.89,52.08 1016.34,52.08 1016.34,293.32 1030.89,293.32
  region: 991.51,52.08 976.98,52.08 976.98,288.39 991.51,288.39
  region: 952.14,52.08 937.61,52.08 937.61,283.47 952.14,283.47
  region: 912.77,52.08 898.25,52.08 898.25,278.56 912.77,278.56
  region: 873.41,52.08 858.86,52.08 858.86,273.64 873.41,273.64
  region: 558.43,52.08 543.9,52.08 543.9,234.27 558.43,234.27
  region: 519.07,52.08 504.54,52.08 504.54,229.34 519.07,229.34
  region: 479.7,52.08 465.17,52.08 465.17,224.42 479.7,224.42
  region: 440.33,52.08 425.81,52.08 425.81,219.49 440.33,219.49
  region: 400.97,52.08 386.42,52.08 386.42,214.59 400.97,214.59
  region: 361.6,52.08 347.05,52.08 347.05,209.66 361.6,209.66
  region: 322.21,52.08 307.69,52.08 307.69,204.73 322.21,204.73
  region: 282.85,52.08 268.32,52.08 268.32,199.81 282.85,199.81
  region: 243.48,52.08 228.95,52.08 228.95,194.88 243.48,194.88
  region: 204.11,52.08 189.59,52.08 189.59,189.98 204.11,189.98
  region: 164.75,52.08 150.2,52.08 150.2,185.05 164.75,185.05
  region: 125.36,52.08 110.83,52.08 110.83,180.12 125.36,180.12
  region: 85.99,52.08 71.47,52.08 71.47,175.2 85.99,175.2
  text "Mighty Gecko" at 32.48,1862.2 h151.57
  text "2.4 GHz" at 39.37,1771.65 h74.8
  text "915 MHz" at 590.55,1771.65 h74.8
  text "19 dBm" at 39.37,1692.91 h74.8
  text "19 dBm" at 590.55,1692.91 h74.8
  text "EFR32MG12" at 413.39,570.87 h74.8
  text "TOUCH SLIDER" at 354.33,295.28 h74.8
EXT_SILKS 22:
  lines w6: 164.28,704.73 164.28,692.92 176.09,692.92 ; 164.28,753.95 164.28,765.76 176.09,765.76 ; 189.87,692.92 201.68,692.92 201.68,704.73 ; 201.68,714.58 201.68,726.39 213.49,726.39 ; 225.31,726.39 238.1,726.39 238.1,738.2 ; 225.31,765.76 238.1,765.76 238.1,753.95
  text "BOARD INFO" at 809.06,1942.91 h62.99
  text "PCB4164A  Rev A02" at 1125.98,1259.84 h62.99 r90
  text "PAVDD" at 268.84,789.8 h62.99
  text "VDCDC" at 386.72,731.31 h47.24
  text "VMCU" at 156.59,726.66 h47.24
EXT_SILKP 23:
  region: 85.99,52.08 71.47,52.08 71.47,175.2 85.99,175.2
  region: 125.36,52.08 110.83,52.08 110.83,180.12 125.36,180.12
  region: 164.75,52.08 150.2,52.08 150.2,185.05 164.75,185.05
  region: 204.11,52.08 189.59,52.08 189.59,189.98 204.11,189.98
  region: 243.48,52.08 228.95,52.08 228.95,194.88 243.48,194.88
  region: 282.85,52.08 268.32,52.08 268.32,199.81 282.85,199.81
  region: 322.21,52.08 307.69,52.08 307.69,204.73 322.21,204.73
  region: 361.6,52.08 347.05,52.08 347.05,209.66 361.6,209.66
  region: 400.97,52.08 386.42,52.08 386.42,214.59 400.97,214.59
  region: 440.33,52.08 425.81,52.08 425.81,219.49 440.33,219.49
  region: 479.7,52.08 465.17,52.08 465.17,224.42 479.7,224.42
  region: 519.07,52.08 504.54,52.08 504.54,229.34 519.07,229.34
  region: 558.43,52.08 543.9,52.08 543.9,234.27 558.43,234.27
  region: 873.41,52.08 858.86,52.08 858.86,273.64 873.41,273.64
  region: 912.77,52.08 898.25,52.08 898.25,278.56 912.77,278.56
  region: 952.14,52.08 937.61,52.08 937.61,283.47 952.14,283.47
  region: 991.51,52.08 976.98,52.08 976.98,288.39 991.51,288.39
  region: 1030.89,52.08 1016.34,52.08 1016.34,293.32 1030.89,293.32
  region: 1070.26,52.08 1055.71,52.08 1055.71,298.25 1070.26,298.25
  region: 1109.63,52.08 1095.1,52.08 1095.1,303.15 1109.63,303.15
  region: 597.82,52.08 583.27,52.08 583.27,239.17 597.82,239.17
  region: 637.19,52.08 622.64,52.08 622.64,244.1 637.19,244.1
  region: 676.55,52.08 662.03,52.08 662.03,249.03 676.55,249.03
  region: 715.92,52.08 701.39,52.08 701.39,253.95 715.92,253.95
  region: 755.29,52.08 740.76,52.08 740.76,258.86 755.29,258.86
  region: 794.65,52.08 780.12,52.08 780.12,263.78 794.65,263.78
  region: 834.04,52.08 819.49,52.08 819.49,268.71 834.04,268.71
  text "Flex Gecko" at 32.48,1862.2 h151.57
  text "2.4 GHz" at 39.37,1771.65 h74.8
  text "915 MHz" at 590.55,1771.65 h74.8
  text "19 dBm" at 39.37,1692.91 h74.8
  text "19 dBm" at 590.55,1692.91 h74.8
  text "EFR32FG12" at 413.39,570.87 h74.8
  text "TOUCH SLIDER" at 354.33,295.28 h74.8
EXT_SILKS 24:
  lines w6: 164.28,704.73 164.28,692.92 176.09,692.92 ; 164.28,753.95 164.28,765.76 176.09,765.76 ; 189.87,692.92 201.68,692.92 201.68,704.73 ; 201.68,714.58 201.68,726.39 213.49,726.39 ; 225.31,726.39 238.1,726.39 238.1,738.2 ; 225.31,765.76 238.1,765.76 238.1,753.95
  text "BOARD INFO" at 809.06,1942.91 h62.99
  text "PCB4253A  Rev A02" at 1125.98,1259.84 h62.99 r90
  text "PAVDD" at 268.84,789.8 h62.99
  text "VDCDC" at 386.72,731.31 h47.24
  text "VMCU" at 156.59,726.66 h47.24
Mechanical 26:
  lines w7.87: -4937.2,-1652.05 -4740.35,-1652.05 ; -4937.2,198.35 -4740.35,198.35 ; -4936.72,2048.74 -4740.35,2048.74 ; -2133.75,-3503.68 -2133.75,-3306.83 ; -2133.75,3779.79 -2133.75,3976.64 ; 673.33,-3503.68 673.33,-3306.83 ; 673.33,3779.79 673.33,3976.64 ; 3476.48,-3503.68 3476.48,-3306.83 ; 3476.48,3779.79 3476.48,3976.64 ; 6086.43,-1652.05 6283.28,-1652.05 ; 6086.43,198.35 6283.28,198.35 ; 6086.43,2048.74 6282.8,2048.74 ; -4936.72,-3503.68 6283.28,-3503.68 6283.28,3976.32 -4936.72,3976.32 -4936.72,-3503.68 ; -4740.35,-3306.83 6086.43,-3306.83 6086.43,3779.79 -4740.35,3779.79 -4740.35,-3306.83
  text "1" at -3641.91,3841.66 h60
  text "2" at -795.17,3841.66 h60
  text "3" at 2063.1,3841.66 h60
  text "4" at 4850.5,3841.66 h60
  text "D" at 6165.09,3088.11 h60
  text "D" at -4862.91,3040.66 h60
  text "C" at -4862.91,1170.79 h60
  text "C" at 6160.09,1170.79 h60
  text "B" at -4862.91,-703.23 h60
  text "B" at 6160.09,-703.23 h60
  text "A" at -4862.91,-2573.31 h60
  text "A" at 6160.09,-2573.31 h60
  text "2" at -795.17,-3442.34 h60
  text "3" at 2051.28,-3442.34 h60
  text "4" at 4834.75,-3442.34 h60
  text "1" at -4135.25,-3972.85 h60
Mechanical 27:
  circle w10: c1520.59,-3031.3 r116.62
  circle w6: c2779.83,-2462.15 r70
  circle w6: c2779.83,-2462.15 r30
  lines w6: 2346.83,-2462.15 2636.83,-2462.15 ; 2689.83,-2462.15 2869.83,-2462.15 ; 2376.83,-2492.15 2376.83,-2432.15 2606.83,-2392.15 2605.83,-2532.15 2376.83,-2492.15
  lines w7.87: 1361.21,-3304.3 1361.21,-2246.83 2936.56,-2246.83 ; 1361.21,-2744.3 6084.21,-2744.3 ; 1361.76,-2601.16 2936.56,-2601.16 ; 2160.21,-3302.3 2160.21,-2747.3 ; 2160.21,-2599.3 2160.21,-2248.3 ; 5298.76,-2743.3 5298.76,-2601.16 ; 5692.47,-2601.16 5692.47,-2246.83 ; 6086.17,-2601.16 2936.56,-2601.16 ; 6086.17,-2246.83 2936.56,-2246.83 ; 2936.56,-2601.16 2936.56,-2246.83
  text "SIZE" at 1440.5,-2325.57 h60
  text "DOC NO" at 3015.3,-2325.57 h60
  text "REV" at 5771.21,-2325.57 h60
  text "PROJECTION" at 2200.21,-2339.3 h60
  text "A02" at 5760.21,-2519.3 h100
  text "A4" at 1544.83,-2537.15 h100
  text "PCB4164/PCB4253" at 3113.71,-2537.15 h100
  text "REF" at 1440.5,-2679.9 h60
  text "SHEET" at 5338.13,-2679.9 h60
  text "1 of 2" at 5725.6,-2720.72 h60
  text "This drawing is confidential and is supplied on the express" at 2179.21,-2861.3 h60
  text "condition that it shall not be loaned, copied or disclosed to any" at 2179.21,-2961.3 h60
  text "other person or used for any purpose without the written consent of" at 2179.21,-3061.3 h60
  text "C" at 1497.21,-3071.3 h80
  text "2017" at 1697.21,-3077.3 h100
  text "SILICON LABS" at 2196.21,-3230.3 h100
Mechanical 28:
  lines w7.87: -4934.2,-1655.05 -4737.35,-1655.05 ; -4934.2,195.35 -4737.35,195.35 ; -4933.72,2045.74 -4737.35,2045.74 ; 6089.43,-1655.05 6286.28,-1655.05 ; 6089.43,2045.74 6286.28,2045.74
  lines w8: -4738.35,-3309.83 -4738.35,3776.79 ; -4737.35,-3309.83 6089.43,-3309.83 6089.43,3776.79 -4737.35,3776.79 ; -2130.75,-3506.68 -2130.75,-3309.83 ; -2130.75,3776.79 -2130.75,3973.64 ; 676.33,-3506.68 676.33,-3309.83 ; 676.33,3776.79 676.33,3973.64 ; 3479.48,-3506.68 3479.48,-3309.83 ; 3479.48,3776.79 3479.48,3973.64 ; -4933.72,-3506.68 -4933.72,3973.32 6286.28,3973.32 6286.28,-3506.68 -4933.72,-3506.68
  text "4" at -3598.91,3838.66 h60
  text "3" at -752.17,3838.66 h60
  text "2" at 2106.1,3838.66 h60
  text "1" at 4893.5,3838.66 h60
  text "D" at 6208.09,3085.11 h60
  text "D" at -4819.91,3037.66 h60
  text "C" at -4819.91,1167.79 h60
  text "C" at 6208.09,1104.8 h60
  text "B" at -4819.91,-706.23 h60
  text "B" at 6208.09,-749.54 h60
  text "A" at 6167.99,-2573.31 h60
  text "A" at -4819.91,-2576.31 h60
  text "A" at 6203.09,-2576.31 h60
  text "3" at -752.17,-3445.34 h60
  text "2" at 2088.28,-3445.34 h60
  text "1" at 4877.75,-3445.34 h60
  text "4" at -4092.25,-3975.85 h60
Mechanical 29:
  circle w10: c-167.95,-3033.83 r116.62
  circle w6: c-1427.2,-2464.68 r70
  circle w6: c-1427.2,-2464.68 r30
  lines w6: -1517.2,-2464.68 -1337.2,-2464.68 ; -1284.2,-2464.68 -994.2,-2464.68 ; -1254.2,-2394.68 -1024.2,-2434.68 -1024.2,-2494.68 -1253.2,-2534.68 -1254.2,-2394.68
  lines w7.87: -4733.53,-2603.69 -1583.93,-2603.69 ; -4733.53,-2249.35 -1583.93,-2249.35 ; -4731.57,-2746.83 -8.57,-2746.83 ; -4339.83,-2603.69 -4339.83,-2249.35 ; -3946.13,-2745.83 -3946.13,-2603.69 ; -807.57,-3304.83 -807.57,-2749.83 ; -807.57,-2601.83 -807.57,-2250.83 ; -9.12,-2603.69 -1583.93,-2603.69 ; -9.12,-2249.35 -1583.93,-2249.35 ; -8.57,-3306.83 -8.57,-2246.83 ; -1583.93,-2603.69 -1583.93,-2249.35
  text "REV" at -4418.57,-2328.09 h60
  text "DOC NO" at -1662.67,-2328.09 h60
  text "SIZE" at -87.87,-2328.09 h60
  text "PROJECTION" at -847.57,-2341.83 h60
  text "A02" at -4407.57,-2521.83 h100
  text "PCB4164/PCB4253" at -1761.08,-2539.68 h100
  text "A4" at -192.2,-2539.68 h100
  text "SHEET" at -3985.5,-2682.43 h60
  text "REF" at -87.87,-2682.43 h60
  text "2 of 2" at -4366.92,-2720.72 h60
  text "This drawing is confidential and is supplied on the express" at -826.57,-2863.83 h60
  text "condition that it shall not be loaned, copied or disclosed to any" at -826.57,-2963.83 h60
  text "other person or used for any purpose without the written consent of" at -826.57,-3063.83 h60
  text "C" at -144.57,-3073.83 h80
  text "2017" at -344.57,-3079.83 h100
  text "SILICON LABS" at -843.57,-3232.83 h100
Mechanical 30:
  lines w7.87: 1361.21,-2246.83 1361.21,-1426.36 6085.62,-1426.36 ; 1361.21,-2091.87 2936.01,-2091.87 ; 1361.21,-1934.39 2936.01,-1934.39 6085.62,-1934.43 ; 1361.21,-1776.91 2936.01,-1776.91 ; 2936.01,-1619.43 6085.62,-1619.43 ; 2936.28,-2246.83 2936.28,-1426.36 ; 2936.28,-1418.09 2936.28,-1016.73 6087.58,-1016.73
  text "BRD4164A: EFR32MG12  2.4 GHz/915 MHz  19 dBm" at 2978.35,-1131.89 h70.87
  text "BRD4253A: EFR32FG12  2.4 GHz/915 MHz  19 dBm" at 2980.31,-1254.92 h70.87
  text "CUSTOMER" at 2979.65,-1501.83 h50
  text "PROJECT NO" at 1419.65,-1541.83 h60
  text "SILICON LABS" at 3666.34,-1574.8 h98.43
  text "DRAWING TITLE" at 2988.65,-1695.83 h60
  text "BRD4164/BRD4253" at 1469.65,-1716.83 h78.74
  text "DATE" at 1419.65,-1861.83 h60
  text "EFR32MG Dual Band Radio Board" at 2985.24,-1863.19 h70.87
  text "2017-01-05" at 2139.65,-1901.83 h60
  text "SHEET NAME" at 2980.65,-2016.83 h60
  text "DRAWN" at 1419.65,-2021.83 h60
  text "CHECK" at 1419.65,-2181.83 h60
